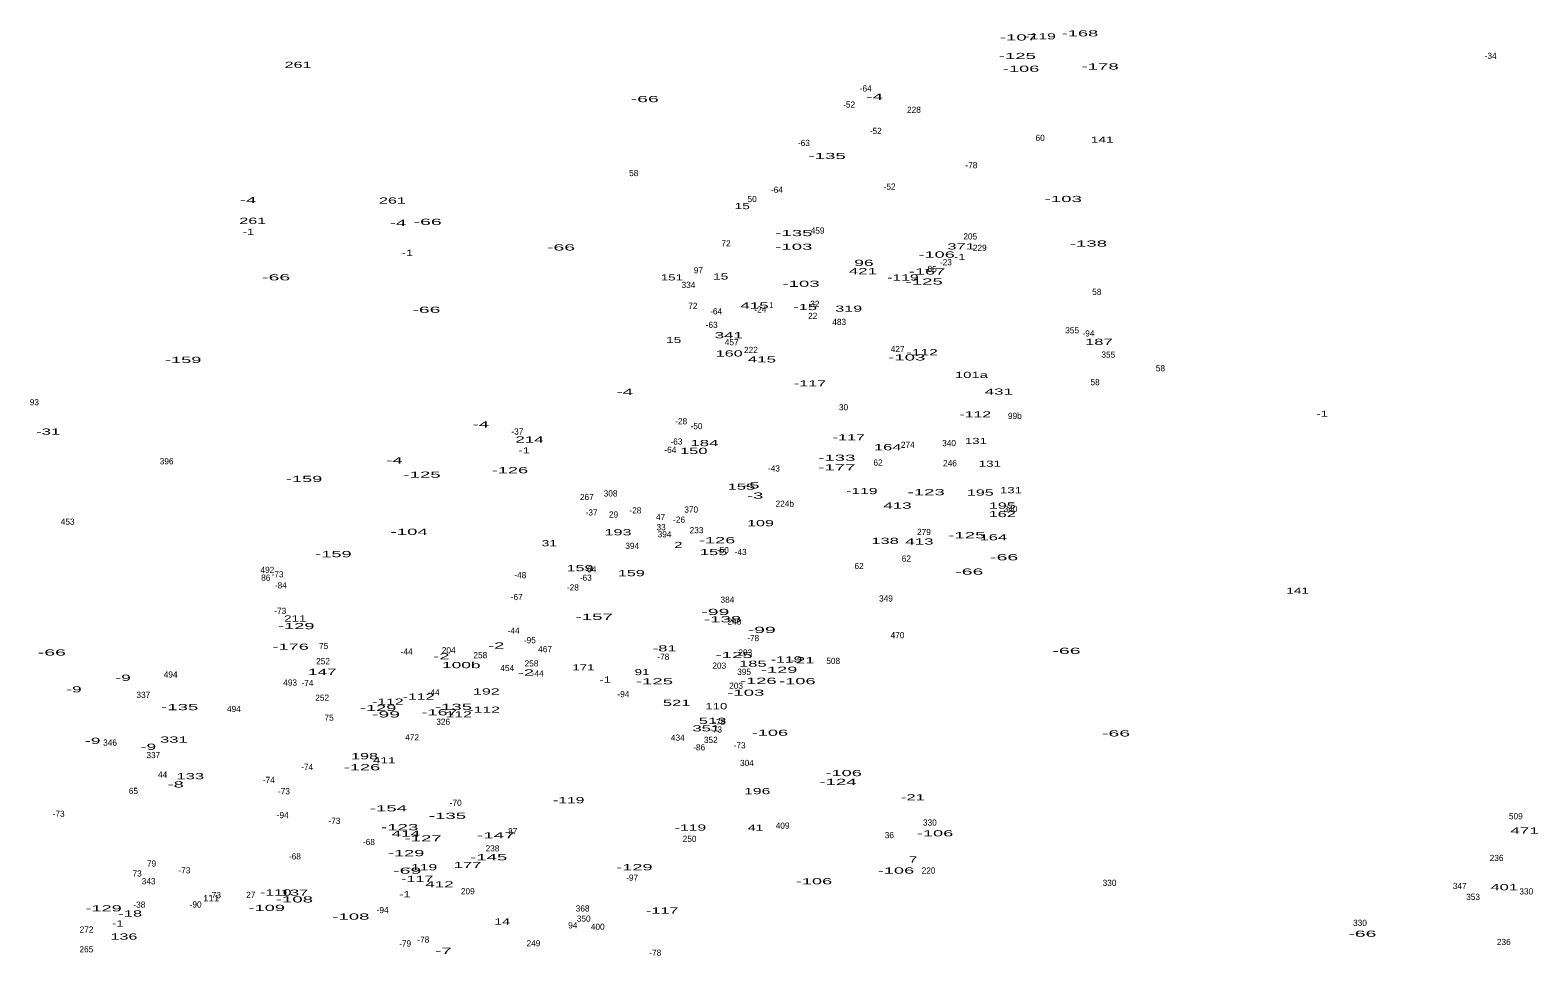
# Model space of a CAD drawing. Extents: x -662280 to -658689, y -991723 to -987042.
# Drawn here: x -661309 to -660334, y -989433 to -988833 of the extents above; entities that cross this region are included whole.
import ezdxf
from ezdxf.enums import TextEntityAlignment as Align

# ---------------------------------------------------------------- set-up
doc = ezdxf.new("R2010")
doc.units = 0
doc.header["$LTSCALE"] = 1.6
doc.layers.add('24', color=7, linetype='Continuous')

msp = doc.modelspace()

# ---------------------------------------------------------------- texts
at = {"layer": '24'}
for s, width, p in [('-107', 2.25, (-660670.001, -988840.18)), ('-119', 1.9, (-660655.971, -988839.46)), ('-168', 2.2, (-660630.175, -988837.55)), ('261', 1.95, (-661136.103, -988857.9)), ('-125', 2.25, (-660670.741, -988852.21)), ('-106', 2.2, (-660668.271, -988860.48)), ('-178', 2.25, (-660617.175, -988858.97)), ('-66', 2.35, (-660911.803, -988880.1)), ('-4', 2.25, (-660763.08, -988878.6)), ('141', 1.65, (-660615.789, -988906.4)), ('-135', 2.25, (-660793.771, -988916.95)), ('-4', 2.25, (-661168.47, -988945.47)), ('261', 1.95, (-661075.043, -988945.75)), ('-103', 2.25, (-660641.007, -988944.77)), ('261', 1.95, (-661165.413, -988958.87)), ('15', 1.65, (-660848.677, -988949.36)), ('-1', 1.55, (-661168.211, -988966.04)), ('-4', 2.25, (-661071.45, -988960.23)), ('-66', 2.35, (-661052.273, -988959.57)), ('-135', 2.25, (-660815.341, -988966.82)), ('-66', 2.35, (-660965.973, -988976.11)), ('-103', 2.25, (-660815.357, -988975.67)), ('371', 2, (-660707.113, -988975.46)), ('-138', 2.25, (-660624.701, -988973.62)), ('-1', 1.55, (-661065.361, -988979.63)), ('96', 2.1, (-660770.001, -988986.13)), ('-106', 2.2, (-660722.951, -988980.73)), ('-1', 1.55, (-660707.991, -988982.33)), ('-66', 2.35, (-661150.273, -988995.48)), ('151', 1.6, (-660894.234, -988995.51)), ('15', 1.65, (-660862.667, -988994.92)), ('421', 2.05, (-660770.633, -988991.46)), ('-119', 1.9, (-660744.711, -988995.58)), ('-167', 2.2, (-660729.119, -988991.68)), ('-103', 2.25, (-660810.677, -988999.64)), ('-125', 2.25, (-660730.941, -988998.19)), ('-66', 2.35, (-661053.083, -989016.46)), ('415', 2.05, (-660840.753, -989013.71)), ('1', 0.65, (-660829.937, -989013.42)), ('-15', 2, (-660808.061, -989014.71)), ('319', 1.95, (-660779.813, -989015.77)), ('15', 1.65, (-660893.077, -989036.01)), ('341', 2.05, (-660857.403, -989032.96)), ('160', 1.95, (-660857.139, -989044.74)), ('-112', 1.9, (-660732.307, -989043.98)), ('187', 2, (-660617.943, -989037.26)), ('-159', 2.2, (-661210.465, -989048.92)), ('415', 2.05, (-660836.023, -989048.61)), ('-103', 2.25, (-660742.277, -989047.31)), ('-117', 1.95, (-660804.871, -989064.14)), ('101a', 1.8, (-660700.415, -989058.62)), ('-4', 2.25, (-660924.7, -989069.63)), ('431', 2.05, (-660682.663, -989069.45)), ('-112', 1.9, (-660697.897, -989084.17)), ('-1', 1.55, (-660473.491, -989083.76)), ('-31', 2, (-661297.791, -989095.33)), ('-4', 2.25, (-661017.89, -989090.69)), ('214', 2.05, (-660986.363, -989100.47)), ('184', 2.05, (-660873.213, -989102.75)), ('-117', 1.95, (-660779.741, -989099.01)), ('131', 1.6, (-660697.524, -989101.4)), ('-4', 2.25, (-661073.78, -989113.99)), ('-1', 1.55, (-660989.851, -989107.49)), ('150', 2, (-660880.114, -989107.84)), ('-133', 2.25, (-660787.531, -989112.25)), ('164', 2, (-660754.598, -989105.39)), ('-125', 2.25, (-661055.891, -989123.2)), ('-126', 2.2, (-660999.035, -989120.33)), ('-177', 2.25, (-660787.489, -989118.45)), ('131', 1.6, (-660688.504, -989116.14)), ('-159', 2.2, (-661132.225, -989125.97)), ('155', 2, (-660849.267, -989130.97)), ('-5', 2.2, (-660842.774, -989130.16)), ('-119', 1.9, (-660771.321, -989133.81)), ('-123', 2.25, (-660729.701, -989134.52)), ('131', 1.6, (-660674.824, -989133.23)), ('-3', 2.2, (-660840.384, -989136.76)), ('413', 2.05, (-660748.253, -989143.2)), ('195', 1.95, (-660694.683, -989134.8)), ('195', 1.95, (-660680.473, -989143.23)), ('162', 1.95, (-660680.483, -989148.71)), ('-104', 2.25, (-661064.232, -989160.2)), ('193', 1.95, (-660929.093, -989160.47)), ('109', 1.95, (-660836.909, -989154.58)), ('-125', 2.25, (-660703.421, -989162.41)), ('164', 2, (-660686.278, -989163.75)), ('31', 1.65, (-660973.547, -989167.57)), ('2', 1.8, (-660890.091, -989168.73)), ('-126', 2.2, (-660864.965, -989165.64)), ('155', 2, (-660867.197, -989173.29)), ('138', 2, (-660756.307, -989166.04)), ('413', 2.05, (-660734.093, -989166.48)), ('-159', 2.2, (-661113.235, -989174.63)), ('-66', 2.35, (-660679.223, -989176.68)), ('159', 1.95, (-660953.643, -989183.7)), ('159', 1.95, (-660920.463, -989186.93)), ('-66', 2.35, (-660701.803, -989185.97)), ('141', 1.65, (-660489.369, -989198.33)), ('-99', 2.35, (-660866.133, -989212.07)), ('-129', 2.2, (-661137.295, -989221.21)), ('211', 1.6, (-661137.954, -989216.27)), ('-157', 2.25, (-660944.505, -989215.24)), ('-138', 2.25, (-660861.461, -989216.81)), ('-99', 2.35, (-660836.113, -989223.71)), ('-66', 2.35, (-661295.403, -989238.31)), ('-176', 2.2, (-661140.929, -989234.57)), ('-2', 2.2, (-661043.414, -989240.78)), ('-2', 2.2, (-661007.904, -989233.79)), ('-81', 2, (-660898.901, -989235.62)), ('-125', 2.25, (-660853.991, -989239.94)), ('-66', 2.35, (-660638.893, -989237.23)), ('147', 2.05, (-661120.428, -989250.88)), ('100b', 2.1, (-661030.515, -989246.46)), ('-2', 2.2, (-660988.684, -989251.27)), ('171', 1.6, (-660951.449, -989247.94)), ('91', 1.6, (-660913.563, -989250.97)), ('185', 2, (-660841.827, -989245.56)), ('-129', 2.2, (-660824.815, -989249.48)), ('-119', 1.9, (-660820.011, -989242.82)), ('-21', 2, (-660809.731, -989243.32)), ('-9', 2.1, (-661249.359, -989254.66)), ('-1', 1.55, (-660937.411, -989255.83)), ('-125', 2.25, (-660905.521, -989256.95)), ('-126', 2.2, (-660838.315, -989256.62)), ('-106', 2.2, (-660813.071, -989256.86)), ('-9', 2.1, (-661281.129, -989262.15)), ('-112', 1.9, (-661078.027, -989270.12)), ('-112', 1.9, (-661058.157, -989266.84)), ('192', 1.95, (-661014.283, -989263.55)), ('521', 2, (-660891.137, -989270.93)), ('-103', 2.25, (-660846.427, -989264.33)), ('-135', 2.25, (-661212.691, -989273.65)), ('-129', 2.2, (-661084.295, -989274.22)), ('-99', 2.35, (-661079.223, -989278.37)), ('-167', 2.2, (-661044.549, -989277.01)), ('-135', 2.25, (-661035.571, -989273.5)), ('-112', 1.9, (-661033.877, -989278.36)), ('-112', 1.9, (-661015.677, -989275.32)), ('110', 1.6, (-660865.48, -989273.06)), ('351', 2, (-660871.987, -989287.41)), ('513', 2, (-660867.887, -989282.58)), ('-106', 2.2, (-660830.821, -989290.25)), ('-66', 2.35, (-660606.833, -989290.66)), ('-9', 2.1, (-661268.989, -989295.47)), ('-9', 2.1, (-661232.959, -989299.32)), ('331', 2, (-661216.477, -989294.69)), ('198', 1.95, (-661093.093, -989305.4)), ('411', 1.65, (-661080.339, -989308.13)), ('133', 2, (-661205.857, -989318.38)), ('-126', 2.2, (-661094.765, -989312.59)), ('-106', 2.2, (-660783.111, -989316.36)), ('-8', 2.2, (-661215.304, -989323.7)), ('196', 1.9, (-660839.017, -989328.04)), ('-124', 2.25, (-660786.776, -989322.09)), ('-154', 2.25, (-661077.636, -989339.15)), ('-119', 1.9, (-660961.001, -989333.88)), ('-21', 2, (-660738.281, -989332.02)), ('-135', 2.25, (-661039.421, -989344.03)), ('-123', 2.25, (-661070.331, -989351.36)), ('414', 2.05, (-661066.369, -989355.56)), ('-127', 2.25, (-661055.215, -989358.6)), ('-147', 2.3, (-661008.191, -989356.69)), ('-119', 1.9, (-660882.221, -989351.64)), ('41', 1.7, (-660840.063, -989351.71)), ('-106', 2.2, (-660723.941, -989355.35)), ('471', 2.05, (-660342.538, -989353.57)), ('-129', 2.2, (-661066.165, -989368.16)), ('-119', 1.9, (-661056.251, -989377.28)), ('177', 2, (-661026.377, -989375.86)), ('-145', 2.25, (-661012.766, -989370.84)), ('-129', 2.2, (-660918.505, -989377.3)), ('7', 1.8, (-660738.196, -989372.3)), ('-69', 2.35, (-661065.473, -989379.54)), ('-117', 1.95, (-661058.991, -989384.84)), ('-106', 2.2, (-660802.301, -989386.4)), ('-106', 2.2, (-660749.281, -989379.45)), ('111', 1.2, (-661192.32, -989397.38)), ('-110', 1.9, (-661150.493, -989393.62)), ('137', 2, (-661138.403, -989393.75)), ('-1', 1.55, (-661067.001, -989394.79)), ('412', 2.05, (-661044.633, -989388.36)), ('401', 2, (-660355.679, -989390.2)), ('-129', 2.2, (-661261.955, -989403.9)), ('-18', 2, (-661244.731, -989407.25)), ('-109', 2.2, (-661156.401, -989403.64)), ('-108', 2.25, (-661138.487, -989398.12)), ('-117', 1.95, (-660900.501, -989405.34)), ('-1', 1.55, (-661252.811, -989413.68)), ('-108', 2.25, (-661101.957, -989409.24)), ('14', 1.7, (-661004.073, -989412.43)), ('136', 1.95, (-661248.783, -989422.17)), ('-66', 2.35, (-660447.463, -989420.34)), ('-7', 2.2, (-661042.069, -989431.48))]:
    msp.add_text(s, height=4, dxfattribs=dict(at, width=width)).set_placement(p, align=Align.CENTER)
for s, p in [('-34', (-660364.439, -988852.14)), ('-64', (-660768.805, -988873.21)), ('-52', (-660779.545, -988883.66)), ('228', (-660737.607, -988887.02)), ('-63', (-660808.84, -988908.49)), ('-52', (-660762.305, -988900.72)), ('60', (-660655.967, -988905.21)), ('58', (-660918.917, -988927.99)), ('-78', (-660700.431, -988922.87)), ('-64', (-660826.275, -988938.78)), ('-52', (-660753.375, -988936.76)), ('50', (-660842.331, -988944.79)), ('459', (-660799.957, -988965.21)), ('72', (-660859.193, -988973.48)), ('205', (-660701.191, -988968.99)), ('229', (-660695.023, -988976.36)), ('-23', (-660716.925, -988985.7)), ('97', (-660877.098, -988990.92)), ('-85', (-660726.705, -988990.06)), ('334', (-660883.501, -989000.37)), ('58', (-660619.297, -989004.89)), ('72', (-660880.673, -989013.99)), ('-64', (-660865.595, -989017.45)), ('-24', (-660837.009, -989016.29)), ('32', (-660801.757, -989012.65)), ('-63', (-660868.49, -989026.2)), ('22', (-660803.127, -989020.46)), ('483', (-660785.991, -989024.34)), ('355', (-660635.247, -989029.78)), ('-94', (-660624.705, -989031.78)), ('457', (-660855.537, -989037.43)), ('222', (-660843.107, -989042.49)), ('427', (-660748.147, -989041.9)), ('355', (-660611.867, -989045.5)), ('58', (-660578.107, -989054.28)), ('58', (-660620.387, -989063.31)), ('93', (-661306.743, -989076.33)), ('30', (-660783.141, -989079.57)), ('99b', (-660672.323, -989085.18)), ('-37', (-660994.211, -989095.25)), ('-28', (-660888.205, -989088.6)), ('-50', (-660878.299, -989091.8)), ('-63', (-660891.27, -989101.76)), ('274', (-660741.607, -989103.85)), ('340', (-660714.895, -989102.78)), ('396', (-661221.148, -989114.54)), ('-64', (-660895.235, -989107.13)), ('-43', (-660828.219, -989119.17)), ('62', (-660760.843, -989115.37)), ('246', (-660714.317, -989115.78)), ('267', (-660949.238, -989137.67)), ('308', (-660933.901, -989135.34)), ('224b', (-660821.206, -989142.01)), ('453', (-661285.191, -989153.63)), ('-37', (-660946.191, -989147.63)), ('29', (-660931.953, -989148.99)), ('-28', (-660917.855, -989146.31)), ('47', (-660901.517, -989150.63)), ('-26', (-660889.6, -989152.33)), ('370', (-660881.747, -989145.78)), ('340', (-660675.065, -989145.39)), ('33', (-660901.217, -989157.2)), ('394', (-660898.977, -989161.8)), ('233', (-660878.307, -989159.12)), ('279', (-660731.138, -989160.31)), ('394', (-660919.897, -989169.24)), ('-50', (-660861.259, -989172.02)), ('-43', (-660849.729, -989173.25)), ('62', (-660773.133, -989182.34)), ('62', (-660742.533, -989177.54)), ('492', (-661155.967, -989184.84)), ('86', (-661157.013, -989189.89)), ('-73', (-661149.391, -989187.71)), ('-48', (-660992.299, -989188.23)), ('-63', (-660949.95, -989189.9)), ('-64', (-660947.055, -989184.5)), ('-84', (-661147.259, -989194.83)), ('-67', (-660994.645, -989202.41)), ('-28', (-660958.305, -989196.19)), ('-73', (-661147.631, -989211.4)), ('384', (-660858.311, -989204.15)), ('349', (-660755.727, -989203.33)), ('240', (-660853.755, -989218.37)), ('-44', (-660996.613, -989224.17)), ('-95', (-660986.13, -989230.35)), ('-78', (-660841.641, -989228.97)), ('470', (-660748.251, -989227.12)), ('75', (-661119.573, -989234.08)), ('-44', (-661065.813, -989237.67)), ('204', (-661038.665, -989236.85)), ('258', (-661018.197, -989240.01)), ('467', (-660976.303, -989236.17)), ('-78', (-660899.781, -989241.04)), ('203', (-660846.751, -989238.36)), ('252', (-661119.967, -989243.98)), ('454', (-661000.786, -989248.35)), ('258', (-660985.077, -989245.35)), ('203', (-660863.581, -989246.83)), ('395', (-660847.513, -989250.82)), ('508', (-660789.861, -989243.76)), ('494', (-661218.561, -989252.57)), ('493', (-661141.247, -989257.78)), ('-74', (-661130.025, -989258.05)), ('-44', (-660980.993, -989251.88)), ('203', (-660852.711, -989259.84)), ('337', (-661236.233, -989265.75)), ('252', (-661120.497, -989267.58)), ('-44', (-661048.363, -989264.07)), ('-94', (-660925.605, -989265.27)), ('494', (-661177.651, -989274.88)), ('75', (-661116.043, -989280.47)), ('326', (-661042.223, -989283.13)), ('-73', (-660865.721, -989288.12)), ('-78', (-660863.601, -989283.3)), ('346', (-661257.777, -989296.63)), ('472', (-661062.337, -989293.22)), ('434', (-660890.406, -989293.43)), ('-86', (-660876.58, -989299.69)), ('352', (-660869.057, -989294.89)), ('-73', (-660850.401, -989298.41)), ('337', (-661229.763, -989304.69)), ('304', (-660845.675, -989309.81)), ('44', (-661223.756, -989317.31)), ('-74', (-661130.225, -989312.33)), ('65', (-661242.673, -989327.92)), ('-74', (-661155.025, -989320.8)), ('-73', (-661145.251, -989328.1)), ('-70', (-661034.124, -989335.6)), ('-73', (-661291.031, -989342.65)), ('-94', (-661146.055, -989343.57)), ('-73', (-661112.591, -989347.27)), ('330', (-660727.321, -989348.38)), ('509', (-660348.177, -989344.28)), ('87', (-660997.223, -989353.97)), ('250', (-660882.771, -989358.94)), ('409', (-660822.611, -989350.39)), ('36', (-660753.533, -989356.49)), ('-68', (-661090.25, -989360.98)), ('238', (-661010.307, -989365.07)), ('79', (-661230.928, -989374.91)), ('-68', (-661138.14, -989370.26)), ('236', (-660360.623, -989371.31)), ('73', (-661240.263, -989381.32)), ('343', (-661232.811, -989386.39)), ('-73', (-661209.651, -989379.3)), ('-97', (-660919.955, -989384.04)), ('220', (-660728.151, -989379.43)), ('330', (-660611.071, -989387.42)), ('-73', (-661189.891, -989395.33)), ('27', (-661166.693, -989395.17)), ('209', (-661026.287, -989392.84)), ('347', (-660384.477, -989389.44)), ('353', (-660375.817, -989396.5)), ('330', (-660341.411, -989392.94)), ('-38', (-661238.795, -989401.53)), ('-90', (-661202.394, -989401.43)), ('-94', (-661081.395, -989405.02)), ('368', (-660951.983, -989403.98)), ('94', (-660958.367, -989414.93)), ('350', (-660951.301, -989410.56)), ('400', (-660942.219, -989415.83)), ('330', (-660449.001, -989413.31)), ('272', (-661272.983, -989417.64)), ('-79', (-661066.855, -989426.7)), ('-78', (-661055.081, -989424.15)), ('249', (-660983.817, -989426.54)), ('236', (-660355.973, -989425.7)), ('265', (-661273.113, -989430.41)), ('-78', (-660905.001, -989432.62))]:
    msp.add_text(s, height=4, dxfattribs=at).set_placement(p, align=Align.CENTER)

doc.saveas('drawing.dxf')
